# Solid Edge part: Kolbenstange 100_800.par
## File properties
Username: ahadarics
Dokumentum tartalom típus: 0
Author: ahadarics
Last saved by: ahadarics
Revision: 97
Sűrűség: 0,000 kg/m^3
Pontosság: 0,990
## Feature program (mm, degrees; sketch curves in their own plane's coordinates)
base feature "unnamed BaseFeature 1"
thread "unnamed Thread 1"
chamfer "Letörés_1"  SetBackValue2 = 20 deg
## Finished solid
Body 1: solid body, 19 faces, 27 edges, 11 vertices.
  Faces by surface: plane 8, cylinder 5, cone 3, torus 3
  Edges by curve: circle 15, line 7, curve on surface 3, ellipse 2
Bounding box of the edges (mm; curved faces can reach further): 100.000 x 100.000 x 988.500, from (-50, -50, -86.75) to (50, 50, 901.75).
Cylindrical faces by radius (mm): R8.75 x1, R10 x1, R12.25 x1, R12.5 x1, R50 x1
Conical faces (half-angle, radius in mm at the cone's reference point): 20 deg R10 x1, 30 deg R12.375 x1, 60 deg R9.375 x1
Toroidal faces (ring radius, tube radius in mm): R9.15 r0.4 x2, R10.45 r1.8 x1
Planar faces by outward normal: +x 1, +z 3, -x 1, -z 1, oblique 2
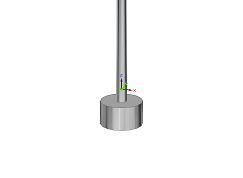
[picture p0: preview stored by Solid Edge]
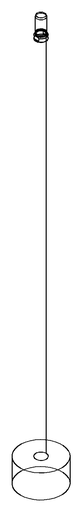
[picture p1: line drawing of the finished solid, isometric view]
